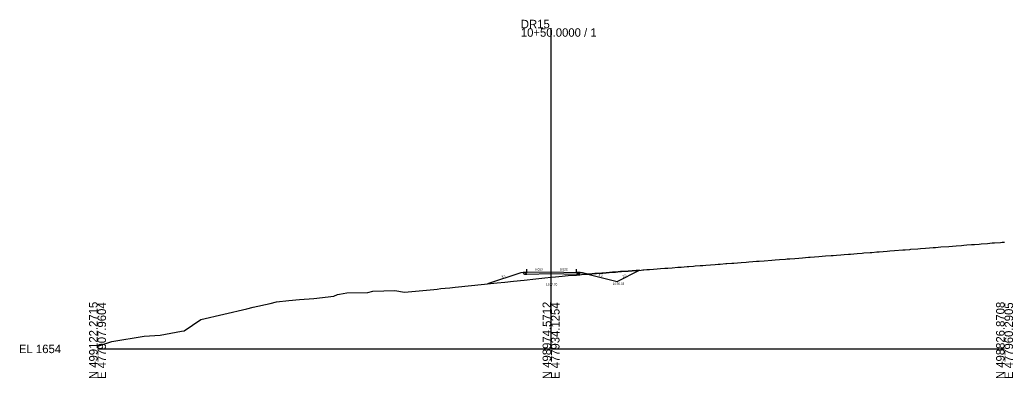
# Model space of a CAD drawing. Extents: x -26 to 303, y -10 to 4126.
# Drawn here: x -25.7 to 302.8, y 490.3 to 609 of the extents above; entities that cross this region are included whole.
import ezdxf

# ---------------------------------------------------------------- set-up
doc = ezdxf.new("R2010")
doc.units = 0
for name, color, linetype in [('Exist Cross Section Cell', 7, 'Continuous'), ('Exist XS Center Line Elevation Label', 7, 'Continuous'), ('Exist XS Ground Line', 7, 'Continuous'), ('Prop Road Sect_ Boring - Material (Outline)', 7, 'Continuous'), ('Prop XS Ditch Slope Text', 7, 'Continuous'), ('Prop XS Ditch Standard Text', 7, 'Continuous'), ('Prop XS Earthwork Shape', 7, 'Continuous'), ('Prop XS EOT Tick Mark', 7, 'Continuous'), ('Prop XS Finish Grade', 7, 'Continuous'), ('Prop XS Finish Grade Earthwork', 7, 'Continuous'), ('Prop XS Finish Grade Pavement', 7, 'Continuous'), ('Prop XS Pvmt Edge Slope', 7, 'Continuous'), ('Prop XS SE Text', 7, 'Continuous'), ('Prop XS Side Slope Text', 7, 'Continuous'), ('Prop XS Subgrade Earthwork', 7, 'Continuous')]:
    doc.layers.add(name, color=color, linetype=linetype)

msp = doc.modelspace()

# ---------------------------------------------------------------- linework, layer by layer
at = {"layer": 'Exist Cross Section Cell'}
for p, q in [((150, 500), (150, 606.18)), ((0, 500), (150, 500)), ((150, 500), (300, 500))]:
    msp.add_line(p, q, dxfattribs=at)
at = {"layer": 'Exist XS Ground Line'}
msp.add_lwpolyline([(0, 500.96), (0.38, 501), (4.68, 502.46), (15.44, 504.19), (20.76, 504.6), (27.77, 505.82), (28.6, 505.96), (34.17, 509.73), (49.38, 513.28), (51.47, 513.79), (57.05, 515.07), (59.22, 515.64), (63.3, 516), (66.83, 516.38), (71.57, 516.67), (78.18, 517.51), (79.33, 518.03), (79.98, 518.14), (82.45, 518.54), (89.41, 518.63), (91.07, 519.07), (98.33, 519.31), (101.52, 518.75), (111.25, 519.71), (112.35, 519.82), (113.59, 519.95), (114.99, 520.1), (116.55, 520.26), (118.31, 520.44), (127.99, 521.43), (129.93, 521.63), (132.15, 521.85), (134.68, 522.12), (137.62, 522.42), (141.08, 522.78), (144.96, 523.16), (147.96, 523.48), (150, 523.7), (151.44, 523.86), (153.73, 524.11), (154.69, 524.18), (155.7, 524.26), (158.42, 524.47), (159.49, 524.55), (160.02, 524.59), (162.1, 524.75), (162.71, 524.79), (163.59, 524.86), (164.45, 524.92), (165.05, 524.97), (166.8, 525.1), (167.15, 525.13), (168.26, 525.22), (170.31, 525.38), (171.35, 525.45), (172.99, 525.58), (173.33, 525.61), (175.51, 525.78), (178.14, 525.97), (179.84, 526.11), (180.36, 526.15), (180.68, 526.18), (181.7, 526.25), (182.53, 526.31), (183.84, 526.41), (185.12, 526.5), (186.22, 526.59), (187.64, 526.7), (188.65, 526.78), (190.02, 526.88), (191.95, 527.03), (192.56, 527.07), (193.01, 527.11), (195.07, 527.26), (195.6, 527.3), (197.16, 527.43), (197.64, 527.46), (199.35, 527.59), (200.16, 527.65), (201.17, 527.73), (202.72, 527.85), (204.26, 527.96), (205.24, 528.04), (205.93, 528.09), (207.81, 528.23), (208.11, 528.26), (209.85, 528.39), (210.41, 528.43), (212.88, 528.62), (214.55, 528.75), (215.4, 528.82), (216.74, 528.92), (217.95, 529.01), (218.88, 529.08), (220.48, 529.2), (223.03, 529.4), (224.17, 529.49), (225.55, 529.6), (227.52, 529.75), (228.1, 529.8), (228.97, 529.86), (230.64, 529.99), (232, 530.1), (233.17, 530.19), (235.14, 530.34), (235.73, 530.39), (238.54, 530.61), (240.8, 530.79), (242.62, 530.93), (243.33, 530.98), (244.39, 531.06), (245.88, 531.18), (246.93, 531.26), (248.41, 531.37), (249.07, 531.42), (251.25, 531.59), (252.91, 531.72), (253.47, 531.77), (255.57, 531.93), (256.05, 531.97), (257.72, 532.09), (258.55, 532.16), (259.8, 532.26), (261.13, 532.36), (262.03, 532.43), (263.63, 532.55), (266.35, 532.77), (267.13, 532.83), (268.71, 532.95), (269.05, 532.98), (271.28, 533.15), (272.17, 533.22), (273.8, 533.35), (275.22, 533.46), (276.35, 533.55), (277.11, 533.61), (278.88, 533.75), (281.53, 533.95), (283.95, 534.14), (285.77, 534.29), (286.5, 534.35), (287.57, 534.43), (289.04, 534.54), (290.09, 534.62), (291.57, 534.73), (292.22, 534.79), (294.4, 534.95), (295.91, 535.07), (296.63, 535.13), (298.71, 535.29), (299.22, 535.33), (300, 535.39)], dxfattribs=at)
at = {"layer": 'Prop Road Sect_ Boring - Material (Outline)'}
for points in [[(142, 525.36), (141.32, 524.68), (140.74, 525.26)], [(159.08, 524.67), (159.66, 525.25), (158.4, 525.35)]]:
    msp.add_lwpolyline(points, close=True, dxfattribs=at)
at = {"layer": 'Prop XS Earthwork Shape'}
for points in [[(162.15, 524.75), (171.84, 522.33), (179.31, 526.06), (178.14, 525.97), (175.51, 525.78), (173.33, 525.61), (172.99, 525.58), (171.35, 525.45), (170.31, 525.38), (168.26, 525.22), (167.15, 525.13), (166.8, 525.1), (165.05, 524.97), (164.45, 524.92), (163.59, 524.86), (162.71, 524.79)], [(162.1, 524.75), (162.15, 524.75), (160.4, 525.19), (159.66, 525.25), (159.08, 524.67), (158.4, 524.68), (150, 524.85), (142, 524.69), (141.32, 524.68), (140.74, 525.26), (140, 525.2), (129, 521.53), (129.93, 521.63), (132.15, 521.85), (134.68, 522.12), (137.62, 522.42), (141.08, 522.78), (144.96, 523.16), (147.96, 523.48), (150, 523.7), (151.44, 523.86), (153.73, 524.11), (154.69, 524.18), (155.7, 524.26), (158.42, 524.47), (159.49, 524.55), (160.02, 524.59)]]:
    msp.add_lwpolyline(points, close=True, dxfattribs=at)
at = {"layer": 'Prop XS EOT Tick Mark'}
for p, q in [((142, 525.36), (142, 526.36)), ((158.4, 525.35), (158.4, 526.35))]:
    msp.add_line(p, q, dxfattribs=at)
at = {"layer": 'Prop XS Finish Grade'}
for p, q in [((142, 525.36), (140.74, 525.26)), ((158.4, 525.35), (159.66, 525.25))]:
    msp.add_line(p, q, dxfattribs=at)
at = {"layer": 'Prop XS Finish Grade Earthwork'}
for p, q in [((171.84, 522.33), (179.31, 526.06)), ((140, 525.2), (129, 521.53)), ((140.74, 525.26), (140, 525.2)), ((159.66, 525.25), (160.4, 525.19)), ((160.4, 525.19), (171.84, 522.33))]:
    msp.add_line(p, q, dxfattribs=at)
at = {"layer": 'Prop XS Finish Grade Pavement'}
for p, q in [((142, 525.36), (150, 525.52)), ((150, 525.52), (158.4, 525.35))]:
    msp.add_line(p, q, dxfattribs=at)
at = {"layer": 'Prop XS Pvmt Edge Slope'}
for p, q in [((142, 525.36), (141.32, 524.68)), ((158.4, 525.35), (159.08, 524.67))]:
    msp.add_line(p, q, dxfattribs=at)
at = {"layer": 'Prop XS Subgrade Earthwork'}
for p, q in [((141.32, 524.68), (140.74, 525.26)), ((142, 524.69), (141.32, 524.68)), ((150, 524.85), (142, 524.69)), ((158.4, 524.68), (150, 524.85)), ((158.4, 524.68), (159.08, 524.67)), ((159.08, 524.67), (159.66, 525.25))]:
    msp.add_line(p, q, dxfattribs=at)

# ---------------------------------------------------------------- texts
at = {"layer": 'Exist Cross Section Cell'}
for s, p in [('DR15', (140, 606.18)), ('10+50.0000 / 1', (140, 603.38)), ('EL 1654', (-26, 498.6))]:
    msp.add_text(s, height=2.8, dxfattribs=at).set_placement(p)
for s, p in [('N 499122.2715', (0, 490)), ('E 477907.9604', (2.8, 490)), ('N 498974.5712', (150, 490)), ('E 477934.1254', (152.8, 490)), ('N 498826.8708', (300, 490)), ('E 477960.2905', (302.8, 490))]:
    msp.add_text(s, height=2.8, rotation=90, dxfattribs=at).set_placement(p)
at = {"layer": 'Exist XS Center Line Elevation Label'}
msp.add_text('1677.70', height=0.75, dxfattribs=at).set_placement((148.33, 520.95))
at = {"layer": 'Prop XS Ditch Slope Text'}
msp.add_text('4:1', height=0.75, rotation=345.9786, dxfattribs=at).set_placement((165.63, 524.18))
at = {"layer": 'Prop XS Ditch Standard Text'}
msp.add_text('1676.33', height=0.75, dxfattribs=at).set_placement((170.45, 521.2))
at = {"layer": 'Prop XS SE Text'}
for rotation, p in [(1.1458, (144.69, 525.91)), (358.8542, (152.89, 525.96))]:
    msp.add_text('0.020', height=0.75, rotation=rotation, dxfattribs=at).set_placement(p)
at = {"layer": 'Prop XS Side Slope Text'}
for s, rotation, p in [('3:1', 18.4349, (133.72, 523.43)), ('2:1', 26.5651, (173.79, 523.59))]:
    msp.add_text(s, height=0.75, rotation=rotation, dxfattribs=at).set_placement(p)

doc.saveas('drawing.dxf')
